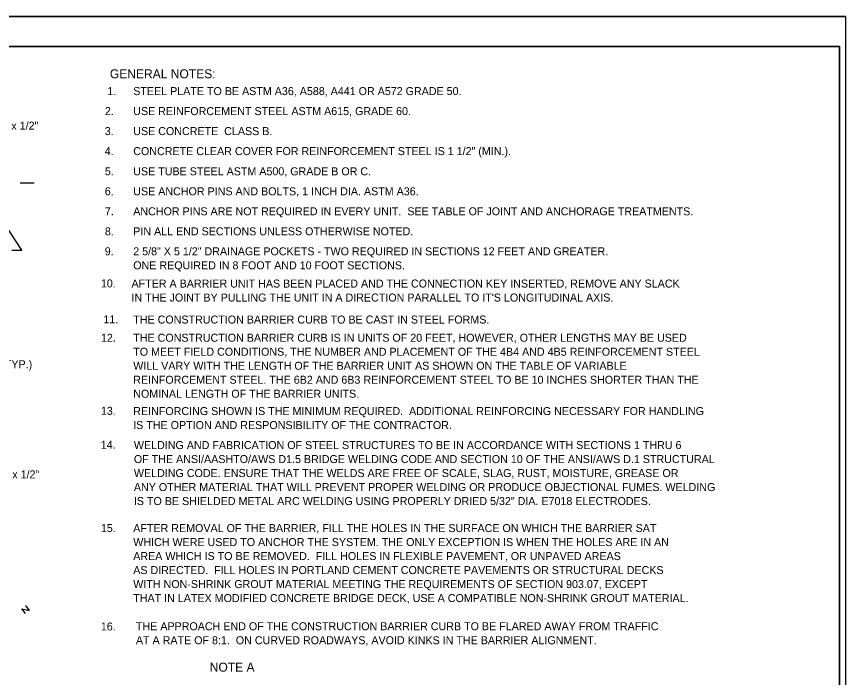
# Model space of a CAD drawing. Extents: x 499883 to 500983, y 499104 to 499764.
# Drawn here: x 500568.6 to 500982.9, y 499433.2 to 499763.6 of the extents above; entities that cross this region are included whole.
import ezdxf

# ---------------------------------------------------------------- set-up
doc = ezdxf.new("R2010")
doc.units = 0
for name, color, linetype in [('1', 7, 'Continuous'), ('24', 7, 'Continuous'), ('41', 7, 'Continuous'), ('5', 7, 'Continuous')]:
    doc.layers.add(name, color=color, linetype=linetype)

msp = doc.modelspace()

# ---------------------------------------------------------------- linework, layer by layer
at = {"layer": '1'}
for p, q in [((500982.94, 499763.64), (499934.77, 499763.64)), ((500979.94, 499748.64), (499989.94, 499748.64)), ((500979.94, 499118.64), (500979.94, 499748.64))]:
    msp.add_line(p, q, dxfattribs=at)
at = {"layer": '41'}
for points in [[(499934.77, 499763.64), (500982.94, 499763.64), (500982.94, 499103.64), (499934.77, 499103.64)], [(499989.94, 499748.64), (500979.94, 499748.64), (500979.94, 499118.64), (499989.94, 499118.64)]]:
    msp.add_lwpolyline(points, close=True, dxfattribs=at)
at = {"layer": '5'}
for p, q in [((500570.43, 499680.53), (500577.38, 499680.53)), ((500573.12, 499469.21), (500574.85, 499466.63)), ((500573.12, 499465.25), (500571.24, 499467.49)), ((500571.24, 499467.49), (500574.85, 499466.63))]:
    msp.add_line(p, q, dxfattribs=at)
msp.add_lwpolyline([(500566.27, 499646.89), (500571.27, 499646.89), (500549.19, 499680.3)], dxfattribs=at)

# ---------------------------------------------------------------- texts
at = {"layer": '24'}
for s, p in [('AFTER A BARRIER UNIT HAS BEEN PLACED AND THE CONNECTION KEY INSERTED, REMOVE ANY SLACK', (500626.06, 499628.16)), ("IN THE JOINT BY PULLING THE UNIT IN A DIRECTION PARALLEL TO IT'S LONGITUDINAL AXIS. ", (500626.06, 499621.16)), ('THE APPROACH END OF THE CONSTRUCTION BARRIER CURB TO BE FLARED AWAY FROM TRAFFIC ', (500628.28, 499456.83)), ('AT A RATE OF 8:1.  ON CURVED ROADWAYS, AVOID KINKS IN THE BARRIER ALIGNMENT.', (500628.28, 499449.83))]:
    msp.add_text(s, height=4, dxfattribs=at).set_placement(p)
at = {"layer": '5'}
for s, height, p in [('GENERAL NOTES:', 4.5, (500615.27, 499732.78)), ('1.', 4, (500613.99, 499724.38)), ('STEEL PLATE TO BE ASTM A36, A588, A441 OR A572 GRADE 50.', 4, (500626.94, 499724.38)), ('2.', 4, (500612.77, 499714.38)), ('USE REINFORCEMENT STEEL ASTM A615, GRADE 60.', 4, (500626.94, 499714.38)), ('4" x 4" x 1/2"', 4, (500549.13, 499707.08)), ('3.', 4, (500612.73, 499704.38)), ('USE CONCRETE  CLASS B.', 4, (500626.94, 499704.38)), ('4.', 4, (500612.68, 499694.38)), ('CONCRETE CLEAR COVER FOR REINFORCEMENT STEEL IS 1 1/2" (MIN.).', 4, (500626.94, 499694.38)), ('5.', 4, (500612.74, 499684.28)), ('USE TUBE STEEL ASTM A500, GRADE B OR C.', 4, (500626.94, 499684.28)), ('6.', 4, (500612.71, 499674.28)), ('USE ANCHOR PINS AND BOLTS, 1 INCH DIA. ASTM A36.', 4, (500626.94, 499674.28)), ('7.', 4, (500612.77, 499664.28)), ('ANCHOR PINS ARE NOT REQUIRED IN EVERY UNIT.  SEE TABLE OF JOINT AND ANCHORAGE TREATMENTS.', 4, (500626.94, 499664.28)), ('8.', 4, (500612.76, 499654.28)), ('PIN ALL END SECTIONS UNLESS OTHERWISE NOTED.', 4, (500626.94, 499654.28)), ('9.', 4, (500612.71, 499644.28)), ('2 5/8" X 5 1/2" DRAINAGE POCKETS - TWO REQUIRED IN SECTIONS 12 FEET AND GREATER.', 4, (500626.94, 499644.28)), ('ONE REQUIRED IN 8 FOOT AND 10 FOOT SECTIONS.', 4, (500626.94, 499637.28)), ('10.', 4, (500610.77, 499628.23)), ('11.', 4, (500612.01, 499610.28)), ('THE CONSTRUCTION BARRIER CURB TO BE CAST IN STEEL FORMS.', 4, (500626.94, 499610.16)), ('12.', 4, (500610.8, 499601.07)), ('THE CONSTRUCTION BARRIER CURB IS IN UNITS OF 20 FEET, HOWEVER, OTHER LENGTHS MAY BE USED ', 4, (500626.94, 499601.07)), ('TO MEET FIELD CONDITIONS, THE NUMBER AND PLACEMENT OF THE 4B4 AND 4B5 REINFORCEMENT STEEL ', 4, (500626.94, 499594.07)), ('(TYP.)', 4, (500560.99, 499587.81)), ('WILL VARY WITH THE LENGTH OF THE BARRIER UNIT AS SHOWN ON THE TABLE OF VARIABLE ', 4, (500626.94, 499587.07)), ('REINFORCEMENT STEEL. THE 6B2 AND 6B3 REINFORCEMENT STEEL TO BE 10 INCHES SHORTER THAN THE', 4, (500626.94, 499580.07)), ('NOMINAL LENGTH OF THE BARRIER UNITS.', 4, (500626.94, 499573.07)), ('13.', 4, (500610.76, 499564.53)), ('REINFORCING SHOWN IS THE MINIMUM REQUIRED.  ADDITIONAL REINFORCING NECESSARY FOR HANDLING ', 4, (500626.94, 499564.41)), ('IS THE OPTION AND RESPONSIBILITY OF THE CONTRACTOR.', 4, (500626.94, 499557.41)), ('14.', 4, (500610.71, 499547.58)), ('WELDING AND FABRICATION OF STEEL STRUCTURES TO BE IN ACCORDANCE WITH SECTIONS 1 THRU 6', 4, (500627.26, 499547.41)), ('OF THE ANSI/AASHTO/AWS D1.5 BRIDGE WELDING CODE AND SECTION 10 OF THE ANSI/AWS D.1 STRUCTURAL ', 4, (500627.26, 499540.41)), ('4" x 4" x 1/2"', 4, (500549.58, 499532.75)), ('WELDING CODE. ENSURE THAT THE WELDS ARE FREE OF SCALE, SLAG, RUST, MOISTURE, GREASE OR ', 4, (500627.26, 499533.41)), ('ANY OTHER MATERIAL THAT WILL PREVENT PROPER WELDING OR PRODUCE OBJECTIONAL FUMES. WELDING', 4, (500627.26, 499526.41)), ('IS TO BE SHIELDED METAL ARC WELDING USING PROPERLY DRIED 5/32" DIA. E7018 ELECTRODES.', 4, (500627.26, 499519.41)), ('15.', 4, (500610.76, 499505.89)), ('AFTER REMOVAL OF THE BARRIER, FILL THE HOLES IN THE SURFACE ON WHICH THE BARRIER SAT ', 4, (500626.94, 499505.91)), ('WHICH WERE USED TO ANCHOR THE SYSTEM. THE ONLY EXCEPTION IS WHEN THE HOLES ARE IN AN', 4, (500626.94, 499498.91)), ('AREA WHICH IS TO BE REMOVED.  FILL HOLES IN FLEXIBLE PAVEMENT, OR UNPAVED AREAS ', 4, (500626.94, 499491.91)), ('AS DIRECTED.  FILL HOLES IN PORTLAND CEMENT CONCRETE PAVEMENTS OR STRUCTURAL DECKS', 4, (500626.94, 499484.91)), ('WITH NON-SHRINK GROUT MATERIAL MEETING THE REQUIREMENTS OF SECTION 903.07, EXCEPT', 4, (500626.94, 499477.91)), ('THAT IN LATEX MODIFIED CONCRETE BRIDGE DECK, USE A COMPATIBLE NON-SHRINK GROUT MATERIAL.', 4, (500626.94, 499470.91)), ('16.', 4, (500610.74, 499456.72)), ('NOTE A', 4.5, (500665.19, 499436.12))]:
    msp.add_text(s, height=height, dxfattribs=at).set_placement(p)

doc.saveas('drawing.dxf')
